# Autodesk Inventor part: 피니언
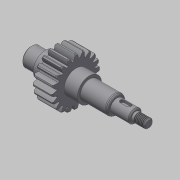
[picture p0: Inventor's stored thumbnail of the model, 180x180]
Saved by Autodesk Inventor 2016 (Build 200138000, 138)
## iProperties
Created: 2019-06
Part Number: 피니언
Material: 스테인리스강
Document SubType Name: Modeling
Designer: mduedu
Density: 8.08 g/cm^3
Appearance: 기본값
Mass: 336.303 g
Surface Area: 112.617 cm^2
Volume: 41.6216 cm^3
Author: mduedu
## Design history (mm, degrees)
sketch "스케치1"
  geometry: L1 (0, 0)-(13, 0); L2 (13, 0)-(13, 8.5); L3 (13, 8.5)-(0, 8.5); L4 (0, 8.5)-(0, 0); L5 (13, 0)-(53, 0); L6 (53, 0)-(53, 11); L7 (53, 11)-(13, 11); L8 (13, 11)-(13, 0); L9 (53, 0)-(78, 0); L10 (78, 0)-(78, 8.5); L11 (78, 8.5)-(53, 8.5); L12 (53, 8.5)-(53, 0); L13 (78, 0)-(95, 0); L14 (95, 0)-(95, 6); L15 (95, 6)-(78, 6); L16 (78, 6)-(78, 0); L17 (95, 0)-(107, 0); L18 (107, 0)-(107, 4); L19 (107, 4)-(95, 4); L20 (95, 4)-(95, 0)
  constraints: 40 end point, 10 parallel, 5 horizontal, 5 perpendicular
  dimensions: "d0" = 107 distance between parallel lines of L18 L4; "d2" = 78 distance between parallel lines of L10 L4; "d3" = 40 distance of L6.end L7.end; "d4" = 25 distance of L10.end L11.end; "d5" = 17 distance of L14.end L15.end; "d6" = 8 diameter of L19 L17; "d7" = 12 diameter of L15 L13; "d8" = 17 diameter of L11 L9; "d9" = 22 diameter of L7 L5; "d10" = 17 diameter of L3 L1
revolve "회전1" sketch "스케치1" stored, may be unused: angle "d11" = 90 deg
node "작업 평면1"
sketch "스케치2"
  geometry: C1 r 17.5 at (0, 0); C2 r 20 at (0, 0); C3 r 22 at (0, 0); 1 further point
  constraints: 3 centre point, 3 coincident
  dimensions: "d13" = 40 diameter of C2; "d15" = 44 diameter of C3; "d16" = 35 diameter of C1
extrude "돌출1" join sketch "스케치2" distance "d17" = 18; taper "d18" = 0 deg
sketch "스케치3"
  geometry: L1 (0, 0)-(22, 0); L2 (0, 0)-(0, 22); L3 (0.57, 0)-(0.57, 22); L4 (1.57, 0)-(1.57, 22); L5 (2.07, 0)-(2.07, 22); A1 r 22 centre (0, 0) between (22, 0) and (0, 22) reference; A2 r 9.495 centre (-7.411, 16.856) between (2.07, 17.377) and (0.57, 22); A3 r 9.495 centre (7.411, 16.856) between (-0.57, 22) and (-2.07, 17.377); A4 r 17.5 centre (0, 0) between (2.07, 17.377) and (-2.07, 17.377); A5 r 22.007 centre (0, 0) between (0.57, 22) and (-0.57, 22); 4 further points
  constraints: 11 point on circle, 10 end point, 6 parallel, 5 point on line, 4 centre point, 3 symmetric about line, 2 coincident, 1 horizontal, 1 perpendicular, 5 other
  dimensions: "d19" = 0.5 distance between parallel lines of L5 L4; "d21" = 1 distance between parallel lines of L3 L4; "d22" = 1.57 distance between parallel lines of L2 L4
extrude "돌출2" join sketch "스케치3" stored distance "d23" = 18; taper "d24" = 0 deg
chamfer "모따기1" distance "d25" = 1; stored, may be unused: second distance "d26" = 2, angle "d27" = 45 deg
fillet "모깎기1" dims "d31" = 0.3
chamfer "모따기2" distance "d32" = 1; stored, may be unused: second distance "d33" = 2, angle "d34" = 45 deg
node "작업 평면2"
sketch "스케치4"
  geometry: L1 (3.5, -2)-(-2.5, -2); L2 (-2.5, 2)-(3.5, 2); L3 (8.5, 8.5)-(8.5, -8.5) reference; A1 r 2 centre (3.5, 0) between (3.5, -2) and (3.5, 2); A2 r 2 centre (-2.5, 0) between (-2.5, 2) and (-2.5, -2); 1 further point
  constraints: 4 end point, 4 point on circle, 4 tangent, 2 centre point, 1 horizontal, 1 horizontal alignment, 1 parallel
  dimensions: "d35" = 3 distance edge to line of A1 L3; "d36" = 10 dimension on A2 A1; "d37" = 4 distance between parallel lines of L2 L1
extrude "돌출3" cut sketch "스케치4" distance "d38" = 2.5; taper "d39" = 0 deg
chamfer "모따기3" distance "d40" = 1.82; stored, may be unused: second distance "d41" = 2, angle "d42" = 30 deg
fillet "모깎기2" dims "d43" = 1, "d44" = 2
chamfer "모따기4" distance "d45" = 1; stored, may be unused: second distance "d46" = 2, angle "d47" = 30 deg
feature "스레드1" dims "d48" = 10, "d49" = 0
chamfer "모따기5" distance "d50" = 1; stored, may be unused: second distance "d51" = 2, angle "d52" = 30 deg
node "솔리드1"
pattern_circular "원형 패턴1" dims angle "d29" = 360 deg
other parameters: "d12" = -12
